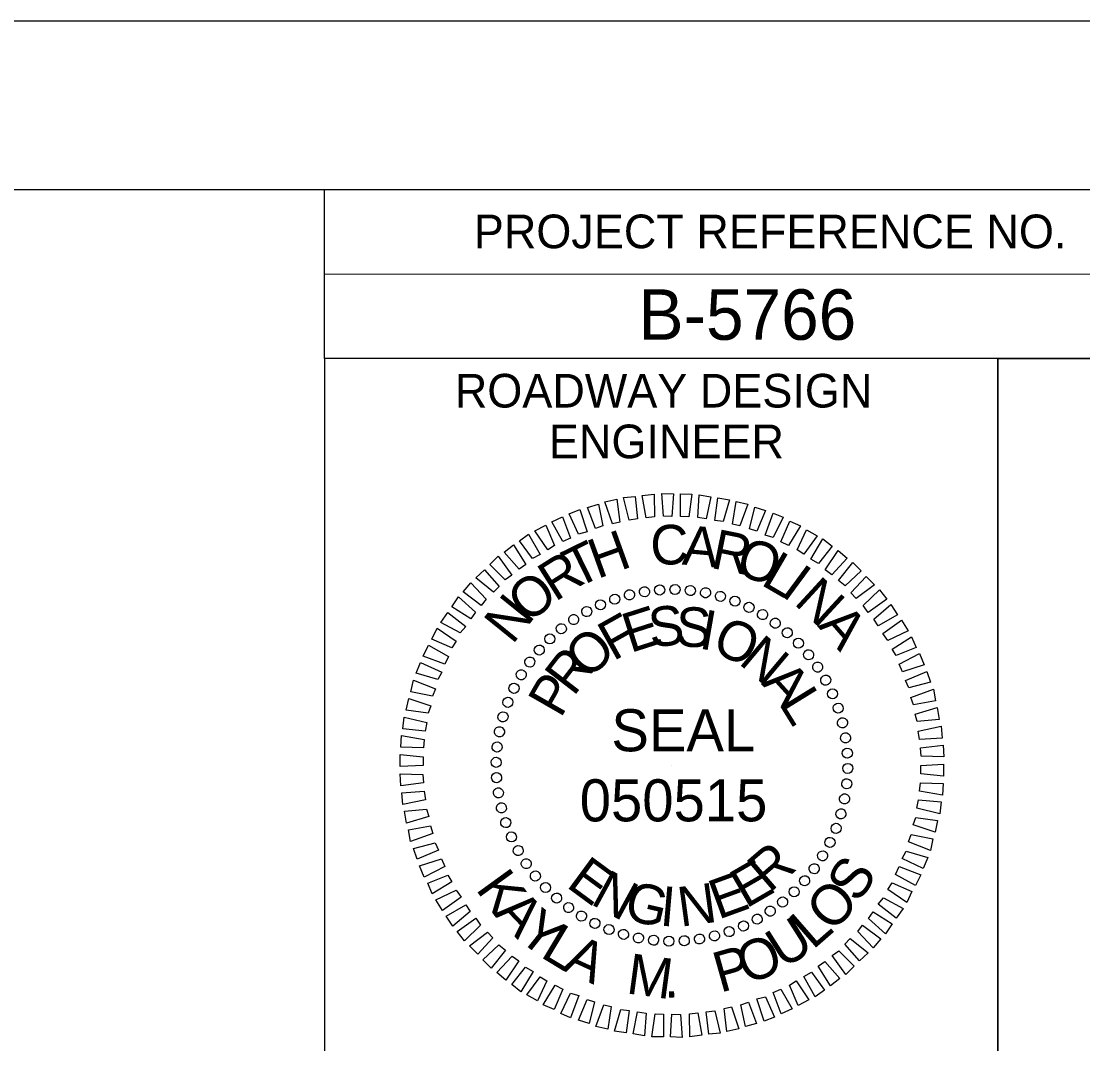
# Model space of a CAD drawing. Extents: x 573076.3 to 573113.7, y -55253.8 to -55199.3.
# Drawn here: x 573106.612 to 573109.767, y -55202.337 to -55199.298 of the extents above; entities that cross this region are included whole.
import ezdxf

# ---------------------------------------------------------------- set-up
doc = ezdxf.new("R2010")
doc.units = 0
for name, color, linetype in [('Prop Dimension', 7, 'Continuous'), ('Prop DSN Text', 7, 'Continuous'), ('Scratch_Level_1', 7, 'Continuous'), ('Sheet Plan CELL', 7, 'Continuous'), ('Sheet Plot Border Inside CELL', 7, 'Continuous')]:
    doc.layers.add(name, color=color, linetype=linetype)

msp = doc.modelspace()

# ---------------------------------------------------------------- linework, layer by layer
at = {"layer": 'Prop Dimension'}
for p, q in [((573108.4648, -55200.9939), (573108.4648, -55200.9939)), ((573108.5094, -55200.9876), (573108.5094, -55200.9876)), ((573108.5553, -55200.9867), (573108.5553, -55200.9867)), ((573108.6011, -55200.9897), (573108.6011, -55200.9897)), ((573108.646, -55200.9971), (573108.646, -55200.9971)), ((573108.3336, -55201.0314), (573108.3336, -55201.0314)), ((573108.3752, -55201.0147), (573108.3752, -55201.0147)), ((573108.419, -55201.0022), (573108.419, -55201.0022)), ((573108.6897, -55201.0064), (573108.6897, -55201.0064)), ((573108.7335, -55201.0209), (573108.7335, -55201.0209)), ((573108.2928, -55201.0522), (573108.2928, -55201.0522)), ((573108.7751, -55201.0397), (573108.7751, -55201.0397)), ((573108.8156, -55201.0605), (573108.8156, -55201.0605)), ((573108.2533, -55201.0762), (573108.2533, -55201.0762)), ((573108.8531, -55201.0867), (573108.8531, -55201.0867)), ((573108.2169, -55201.1022), (573108.2169, -55201.1022)), ((573108.8897, -55201.1147), (573108.8897, -55201.1147)), ((573108.1825, -55201.1334), (573108.1825, -55201.1334)), ((573108.9218, -55201.1459), (573108.9218, -55201.1459)), ((573108.1512, -55201.1658), (573108.1512, -55201.1658)), ((573108.9531, -55201.1804), (573108.9531, -55201.1804)), ((573108.1232, -55201.2021), (573108.1232, -55201.2021)), ((573108.9792, -55201.2167), (573108.9792, -55201.2167)), ((573108.0971, -55201.2396), (573108.0971, -55201.2396)), ((573108.0762, -55201.2804), (573108.0762, -55201.2804)), ((573109.0031, -55201.2563), (573109.0031, -55201.2563)), ((573109.0239, -55201.297), (573109.0239, -55201.297)), ((573108.0575, -55201.322), (573108.0575, -55201.322)), ((573109.0405, -55201.3387), (573109.0405, -55201.3387)), ((573108.0429, -55201.3658), (573108.0429, -55201.3658)), ((573108.0337, -55201.4095), (573108.0337, -55201.4095)), ((573109.053, -55201.3824), (573109.053, -55201.3824)), ((573109.0614, -55201.4282), (573109.0614, -55201.4282)), ((573108.0262, -55201.4542), (573108.0262, -55201.4542)), ((573109.0676, -55201.4729), (573109.0676, -55201.4729)), ((573108.0232, -55201.5), (573108.0232, -55201.5)), ((573108.546, -55201.5095), (573108.546, -55201.5095)), ((573109.0688, -55201.5187), (573109.0688, -55201.5187)), ((573108.0242, -55201.5458), (573108.0242, -55201.5458)), ((573109.0655, -55201.5645), (573109.0655, -55201.5645)), ((573108.0304, -55201.5907), (573108.0304, -55201.5907)), ((573109.0584, -55201.6094), (573109.0584, -55201.6094)), ((573108.0387, -55201.6365), (573108.0387, -55201.6365)), ((573109.0489, -55201.6532), (573109.0489, -55201.6532)), ((573108.0512, -55201.6802), (573108.0512, -55201.6802)), ((573108.0679, -55201.7219), (573108.0679, -55201.7219)), ((573109.0343, -55201.6969), (573109.0343, -55201.6969)), ((573109.0156, -55201.7386), (573109.0156, -55201.7386)), ((573108.0887, -55201.7624), (573108.0887, -55201.7624)), ((573108.9947, -55201.7791), (573108.9947, -55201.7791)), ((573108.1128, -55201.802), (573108.1128, -55201.802)), ((573108.9688, -55201.8166), (573108.9688, -55201.8166)), ((573108.1387, -55201.8385), (573108.1387, -55201.8385)), ((573108.9406, -55201.8531), (573108.9406, -55201.8531)), ((573108.17, -55201.8728), (573108.17, -55201.8728)), ((573108.2024, -55201.904), (573108.2024, -55201.904)), ((573108.9093, -55201.8853), (573108.9093, -55201.8853)), ((573108.2387, -55201.9323), (573108.2387, -55201.9323)), ((573108.8385, -55201.9427), (573108.8385, -55201.9427)), ((573108.8751, -55201.9165), (573108.8751, -55201.9165)), ((573108.2762, -55201.9582), (573108.2762, -55201.9582)), ((573108.3169, -55201.979), (573108.3169, -55201.979)), ((573108.7989, -55201.9665), (573108.7989, -55201.9665)), ((573108.3586, -55201.9977), (573108.3586, -55201.9977)), ((573108.7168, -55202.004), (573108.7168, -55202.004)), ((573108.7584, -55201.9873), (573108.7584, -55201.9873)), ((573108.4023, -55202.0123), (573108.4023, -55202.0123)), ((573108.446, -55202.0218), (573108.446, -55202.0218)), ((573108.4907, -55202.029), (573108.4907, -55202.029)), ((573108.5365, -55202.0322), (573108.5365, -55202.0322)), ((573108.5823, -55202.0311), (573108.5823, -55202.0311)), ((573108.6272, -55202.0248), (573108.6272, -55202.0248)), ((573108.6731, -55202.0165), (573108.6731, -55202.0165))]:
    msp.add_line(p, q, dxfattribs=at)
for points in [[(573108.419, -55200.7805), (573108.4023, -55200.7138), (573108.4365, -55200.7106), (573108.444, -55200.7773)], [(573108.4689, -55200.7742), (573108.4574, -55200.7076), (573108.4928, -55200.7034), (573108.4939, -55200.771)], [(573108.521, -55200.7689), (573108.5157, -55200.7014), (573108.5502, -55200.7023), (573108.546, -55200.7701)], [(573108.571, -55200.7701), (573108.571, -55200.7023), (573108.6053, -55200.7034), (573108.596, -55200.771)], [(573108.6231, -55200.7731), (573108.6272, -55200.7055), (573108.6615, -55200.7118), (573108.6481, -55200.7773)], [(573108.6731, -55200.7814), (573108.6823, -55200.7148), (573108.7168, -55200.7201), (573108.6981, -55200.7847)], [(573108.319, -55200.8055), (573108.2949, -55200.743), (573108.3273, -55200.7335), (573108.3407, -55200.7981)], [(573108.369, -55200.7918), (573108.347, -55200.7263), (573108.3824, -55200.7189), (573108.3907, -55200.7867)], [(573108.7261, -55200.793), (573108.7365, -55200.7252), (573108.7719, -55200.7335), (573108.748, -55200.7981)], [(573108.776, -55200.8064), (573108.7918, -55200.7418), (573108.8239, -55200.7523), (573108.798, -55200.8138)], [(573108.222, -55200.8439), (573108.1887, -55200.7856), (573108.2211, -55200.771), (573108.2449, -55200.8346)], [(573108.2678, -55200.8221), (573108.2408, -55200.7617), (573108.272, -55200.7493), (573108.294, -55200.8159)], [(573108.823, -55200.8252), (573108.8468, -55200.7597), (573108.876, -55200.7722), (573108.8469, -55200.8326)], [(573108.1774, -55200.8689), (573108.1387, -55200.8127), (573108.1711, -55200.796), (573108.197, -55200.8564)], [(573108.8698, -55200.8451), (573108.8959, -55200.7835), (573108.9281, -55200.7981), (573108.8927, -55200.8564)], [(573108.9177, -55200.8689), (573108.9459, -55200.8097), (573108.9771, -55200.8272), (573108.9376, -55200.8814)], [(573108.1315, -55200.895), (573108.0929, -55200.8418), (573108.12, -55200.8222), (573108.1544, -55200.8825)], [(573108.9584, -55200.8971), (573108.9947, -55200.8367), (573109.0218, -55200.8585), (573108.9813, -55200.9096)], [(573108.092, -55200.9263), (573108.0471, -55200.8763), (573108.0753, -55200.8543), (573108.1116, -55200.9126)], [(573109.001, -55200.9284), (573109.0396, -55200.871), (573109.0667, -55200.8939), (573109.0209, -55200.943)], [(573108.0503, -55200.9585), (573108.0045, -55200.9126), (573108.0295, -55200.8876), (573108.07, -55200.9439)], [(573109.0405, -55200.9605), (573109.0834, -55200.9064), (573109.1084, -55200.9314), (573109.0604, -55200.9763)], [(573108.0158, -55200.995), (573107.9628, -55200.9522), (573107.9888, -55200.9284), (573108.0325, -55200.9784)], [(573107.9795, -55201.0346), (573107.9253, -55200.9939), (573107.9483, -55200.9668), (573107.9941, -55201.0158)], [(573109.078, -55200.9971), (573109.1229, -55200.948), (573109.1479, -55200.973), (573109.0938, -55201.0138)], [(573109.1146, -55201.0346), (573109.1625, -55200.9876), (573109.1843, -55201.0158), (573109.1292, -55201.0554)], [(573107.9483, -55201.0742), (573107.892, -55201.0388), (573107.9117, -55201.0084), (573107.9617, -55201.0543)], [(573109.1458, -55201.0751), (573109.1968, -55201.0314), (573109.2167, -55201.0617), (573109.1583, -55201.095)], [(573107.917, -55201.1158), (573107.8587, -55201.0846), (573107.8795, -55201.0554), (573107.9337, -55201.0971)], [(573109.1729, -55201.1179), (573109.228, -55201.0783), (573109.2479, -55201.1096), (573109.1875, -55201.1387)], [(573107.892, -55201.1605), (573107.8325, -55201.1346), (573107.8483, -55201.1022), (573107.9045, -55201.1408)], [(573109.2, -55201.1637), (573109.2583, -55201.1272), (573109.2717, -55201.1596), (573109.2125, -55201.1834)], [(573107.8712, -55201.2084), (573107.8066, -55201.1846), (573107.8221, -55201.1522), (573107.8816, -55201.1855)], [(573109.2208, -55201.2084), (573109.2821, -55201.1771), (573109.2958, -55201.2105), (573109.2312, -55201.2313)], [(573107.8504, -55201.2542), (573107.7858, -55201.2355), (573107.7992, -55201.2033), (573107.8617, -55201.2325)], [(573109.2396, -55201.2574), (573109.303, -55201.2304), (573109.3145, -55201.2625), (573109.25, -55201.2792)], [(573107.8346, -55201.3042), (573107.7701, -55201.2908), (573107.7775, -55201.2563), (573107.843, -55201.2824)], [(573109.2562, -55201.3074), (573109.3229, -55201.2834), (573109.3291, -55201.3178), (573109.2634, -55201.3292)], [(573107.8212, -55201.3542), (573107.7566, -55201.3458), (573107.7638, -55201.3104), (573107.8295, -55201.3324)], [(573109.2687, -55201.3574), (573109.3342, -55201.3375), (573109.3405, -55201.3729), (573109.275, -55201.3792)], [(573107.8129, -55201.4074), (573107.7462, -55201.4012), (573107.7504, -55201.3658), (573107.818, -55201.3824)], [(573109.278, -55201.4074), (573109.3458, -55201.3928), (573109.3488, -55201.4282), (573109.2821, -55201.4324)], [(573107.8076, -55201.4574), (573107.74, -55201.4553), (573107.7421, -55201.4208), (573107.8096, -55201.4324)], [(573109.2842, -55201.4574), (573109.352, -55201.4491), (573109.3541, -55201.4845), (573109.2863, -55201.4824)], [(573107.8066, -55201.5095), (573107.7388, -55201.5125), (573107.7388, -55201.4771), (573107.8066, -55201.4845)], [(573109.2854, -55201.5095), (573109.353, -55201.5062), (573109.353, -55201.5416), (573109.2854, -55201.5345)], [(573107.8076, -55201.5615), (573107.74, -55201.5699), (573107.7379, -55201.5345), (573107.8055, -55201.5365)], [(573109.2842, -55201.5615), (573109.352, -55201.5636), (573109.35, -55201.5979), (573109.2821, -55201.5865)], [(573107.8138, -55201.6115), (573107.7462, -55201.6261), (573107.743, -55201.5907), (573107.8096, -55201.5865)], [(573109.2791, -55201.6115), (573109.3458, -55201.6178), (573109.3416, -55201.6532), (573109.2738, -55201.6365)], [(573107.8233, -55201.6615), (573107.7576, -55201.6812), (573107.7513, -55201.6458), (573107.817, -55201.6395)], [(573107.8358, -55201.7115), (573107.7691, -55201.7353), (573107.7629, -55201.7011), (573107.8284, -55201.6895)], [(573109.2708, -55201.6645), (573109.3354, -55201.6728), (573109.328, -55201.7082), (573109.2625, -55201.6865)], [(573109.2572, -55201.7145), (573109.3217, -55201.7281), (573109.3145, -55201.7624), (573109.2488, -55201.7365)], [(573107.8524, -55201.7615), (573107.7888, -55201.7885), (573107.7775, -55201.7562), (573107.842, -55201.7395)], [(573107.8712, -55201.8103), (573107.8096, -55201.8415), (573107.7962, -55201.8082), (573107.8608, -55201.7874)], [(573109.2416, -55201.7645), (573109.3062, -55201.7832), (573109.2926, -55201.8156), (573109.2301, -55201.7865)], [(573109.2208, -55201.8103), (573109.2854, -55201.8344), (573109.2696, -55201.8665), (573109.2104, -55201.8332)], [(573107.892, -55201.8552), (573107.8337, -55201.8915), (573107.8201, -55201.8594), (573107.8795, -55201.8353)], [(573107.9191, -55201.901), (573107.8638, -55201.9406), (573107.8441, -55201.9093), (573107.9045, -55201.8802)], [(573109.2, -55201.8582), (573109.2592, -55201.8844), (573109.2437, -55201.9165), (573109.1875, -55201.8781)], [(573109.175, -55201.9031), (573109.2333, -55201.9343), (573109.2125, -55201.9635), (573109.1583, -55201.9218)], [(573107.9462, -55201.9436), (573107.895, -55201.9873), (573107.8754, -55201.9573), (573107.9337, -55201.9239)], [(573109.1438, -55201.9448), (573109.2, -55201.9802), (573109.1801, -55202.0102), (573109.1301, -55201.9644)], [(573107.9774, -55201.9843), (573107.9295, -55202.0311), (573107.9075, -55202.0031), (573107.9628, -55201.9635)], [(573108.0137, -55202.0218), (573107.9691, -55202.0706), (573107.9441, -55202.0457), (573107.9982, -55202.0052)], [(573109.1125, -55201.9843), (573109.1667, -55202.0248), (573109.1438, -55202.0519), (573109.0979, -55202.0031)], [(573109.076, -55202.0239), (573109.1292, -55202.0665), (573109.103, -55202.0906), (573109.0593, -55202.0406)], [(573108.0512, -55202.0581), (573108.0087, -55202.1123), (573107.9837, -55202.0873), (573108.0316, -55202.0426)], [(573109.0417, -55202.0602), (573109.0875, -55202.1061), (573109.0625, -55202.131), (573109.0218, -55202.0748)], [(573108.0908, -55202.0906), (573108.0524, -55202.1477), (573108.0253, -55202.1248), (573108.0711, -55202.076)], [(573109.0001, -55202.0926), (573109.0447, -55202.1426), (573109.0167, -55202.1644), (573108.9801, -55202.1061)], [(573108.1336, -55202.1218), (573108.0971, -55202.1822), (573108.07, -55202.1602), (573108.1107, -55202.1093)], [(573108.9605, -55202.1239), (573108.9989, -55202.1769), (573108.9718, -55202.1968), (573108.9376, -55202.1364)], [(573108.1741, -55202.1498), (573108.1461, -55202.2093), (573108.1149, -55202.1914), (573108.1544, -55202.1373)], [(573108.222, -55202.1739), (573108.1961, -55202.2352), (573108.1637, -55202.2206), (573108.1991, -55202.1623)], [(573108.9147, -55202.1498), (573108.9531, -55202.206), (573108.9209, -55202.2227), (573108.8948, -55202.1623)], [(573108.269, -55202.1935), (573108.2449, -55202.2592), (573108.2158, -55202.2468), (573108.2449, -55202.1864)], [(573108.8239, -55202.1968), (573108.851, -55202.2572), (573108.8198, -55202.2697), (573108.798, -55202.203)], [(573108.8698, -55202.1748), (573108.9031, -55202.2331), (573108.8709, -55202.2477), (573108.8468, -55202.1843)], [(573108.3158, -55202.2123), (573108.3002, -55202.2768), (573108.2678, -55202.2664), (573108.294, -55202.2051)], [(573108.3657, -55202.2259), (573108.3553, -55202.2935), (573108.3199, -55202.2852), (573108.344, -55202.2206)], [(573108.723, -55202.2269), (573108.7448, -55202.2926), (573108.7094, -55202.2997), (573108.7011, -55202.2322)], [(573108.773, -55202.2134), (573108.7969, -55202.2759), (573108.7647, -55202.2852), (573108.751, -55202.2206)], [(573108.419, -55202.2373), (573108.4095, -55202.3039), (573108.3752, -55202.2988), (573108.394, -55202.2343)], [(573108.4689, -55202.2456), (573108.4648, -55202.3134), (573108.4303, -55202.3072), (573108.444, -55202.2414)], [(573108.521, -55202.2488), (573108.521, -55202.3164), (573108.4865, -55202.3155), (573108.496, -55202.2477)], [(573108.571, -55202.2498), (573108.5761, -55202.3176), (573108.5418, -55202.3164), (573108.546, -55202.2488)], [(573108.6231, -55202.2447), (573108.6344, -55202.3113), (573108.599, -55202.3155), (573108.5981, -55202.2477)], [(573108.6731, -55202.2384), (573108.6897, -55202.3051), (573108.6552, -55202.3081), (573108.6481, -55202.2414)]]:
    msp.add_lwpolyline(points, close=True, dxfattribs=at)
for centre, major_axis in [((573108.376, -55201.0155), (-0.0049, 0.0142)), ((573108.4196, -55201.0026), (-0.0036, 0.0146)), ((573108.4643, -55200.9935), (-0.0023, 0.0148)), ((573108.5096, -55200.9883), (-0.001, 0.015)), ((573108.5551, -55200.9871), (0.0003, 0.015)), ((573108.6006, -55200.9899), (0.0016, 0.0149)), ((573108.6457, -55200.9966), (0.0029, 0.0147)), ((573108.69, -55201.0073), (0.0041, 0.0144)), ((573108.3336, -55201.0322), (-0.0061, 0.0137)), ((573108.7332, -55201.0217), (0.0054, 0.014)), ((573108.775, -55201.0399), (0.0066, 0.0135)), ((573108.2539, -55201.0763), (-0.0084, 0.0124)), ((573108.2928, -55201.0525), (-0.0073, 0.0131)), ((573108.8151, -55201.0616), (0.0077, 0.0129)), ((573108.2173, -55201.1034), (-0.0094, 0.0117)), ((573108.8531, -55201.0868), (0.0088, 0.0121)), ((573108.1832, -55201.1336), (-0.0104, 0.0108)), ((573108.8887, -55201.1152), (0.0098, 0.0113)), ((573108.1518, -55201.1667), (-0.0113, 0.0098)), ((573108.9218, -55201.1465), (0.0108, 0.0104)), ((573108.1234, -55201.2024), (-0.0121, 0.0088)), ((573108.952, -55201.1807), (0.0117, 0.0094)), ((573108.9791, -55201.2173), (0.0124, 0.0084)), ((573108.0983, -55201.2404), (-0.0129, 0.0077)), ((573109.0029, -55201.2562), (0.0131, 0.0073)), ((573108.0765, -55201.2804), (-0.0135, 0.0066)), ((573109.0232, -55201.2969), (0.0137, 0.0061)), ((573108.0584, -55201.3222), (-0.014, 0.0054)), ((573109.0399, -55201.3393), (0.0142, 0.0049)), ((573108.0439, -55201.3654), (-0.0144, 0.0041)), ((573109.0529, -55201.383), (0.0146, 0.0036)), ((573108.0333, -55201.4097), (-0.0147, 0.0029)), ((573109.0619, -55201.4277), (0.0148, 0.0023)), ((573108.0265, -55201.4548), (-0.0149, 0.0016)), ((573109.0671, -55201.473), (0.015, 0.001)), ((573108.0237, -55201.5003), (-0.015, 0.0003)), ((573109.0683, -55201.5185), (0.015, -0.0003)), ((573108.0249, -55201.5458), (-0.015, -0.001)), ((573109.0655, -55201.564), (0.0149, -0.0016)), ((573108.0301, -55201.5911), (-0.0148, -0.0023)), ((573109.0588, -55201.6091), (0.0147, -0.0029)), ((573108.0392, -55201.6358), (-0.0146, -0.0036)), ((573108.0521, -55201.6795), (-0.0142, -0.0049)), ((573109.0481, -55201.6534), (0.0144, -0.0041)), ((573109.0337, -55201.6966), (0.014, -0.0054)), ((573108.0688, -55201.7219), (-0.0137, -0.0061)), ((573109.0155, -55201.7384), (0.0135, -0.0066)), ((573108.0892, -55201.7626), (-0.0131, -0.0073)), ((573108.113, -55201.8015), (-0.0124, -0.0084)), ((573108.9938, -55201.7784), (0.0129, -0.0077)), ((573108.1401, -55201.8381), (-0.0117, -0.0094)), ((573108.9686, -55201.8164), (0.0121, -0.0088)), ((573108.9402, -55201.8521), (0.0113, -0.0098)), ((573108.1703, -55201.8723), (-0.0108, -0.0104)), ((573108.9089, -55201.8851), (0.0104, -0.0108)), ((573108.2033, -55201.9036), (-0.0098, -0.0113)), ((573108.239, -55201.932), (-0.0088, -0.0121)), ((573108.8747, -55201.9153), (0.0094, -0.0117)), ((573108.277, -55201.9571), (-0.0077, -0.0129)), ((573108.8381, -55201.9424), (0.0084, -0.0124)), ((573108.317, -55201.9789), (-0.0066, -0.0135)), ((573108.7585, -55201.9866), (0.0061, -0.0137)), ((573108.7993, -55201.9663), (0.0073, -0.0131)), ((573108.3588, -55201.9971), (-0.0054, -0.014)), ((573108.402, -55202.0115), (-0.0041, -0.0144)), ((573108.4463, -55202.0222), (-0.0029, -0.0147)), ((573108.6277, -55202.0253), (0.0023, -0.0148)), ((573108.6724, -55202.0162), (0.0036, -0.0146)), ((573108.7161, -55202.0033), (0.0049, -0.0142)), ((573108.4914, -55202.0289), (-0.0016, -0.0149)), ((573108.5369, -55202.0317), (-0.0003, -0.015)), ((573108.5825, -55202.0305), (0.001, -0.015))]:
    msp.add_ellipse(centre, major_axis=major_axis, ratio=0.999708, dxfattribs=at)
at = {"layer": 'Scratch_Level_1'}
msp.add_line((573108.546, -55201.5095), (573108.546, -55201.5095), dxfattribs=at)
at = {"layer": 'Sheet Plan CELL'}
for p, q in [((573107.5132, -55200.0494), (573111.5142, -55200.0497)), ((573109.5142, -55200.3002), (573109.5144, -55202.5494))]:
    msp.add_line(p, q, dxfattribs=at)
for points in [[(573081.5142, -55199.7984), (573111.5142, -55199.7984), (573111.5142, -55220.7984), (573081.5142, -55220.7984)], [(573107.5132, -55199.7984), (573111.5142, -55199.7984), (573111.5142, -55200.3002), (573107.5132, -55200.3002)], [(573109.5142, -55200.3002), (573107.5132, -55200.3002), (573107.5132, -55202.5502), (573109.5142, -55202.5502)], [(573109.5142, -55200.3002), (573111.5142, -55200.3002), (573111.5142, -55202.5502), (573109.5142, -55202.5502)]]:
    msp.add_lwpolyline(points, close=True, dxfattribs=at)
at = {"layer": 'Sheet Plot Border Inside CELL'}
msp.add_lwpolyline([(573112.0142, -55199.2984), (573078.0142, -55199.2984), (573078.0142, -55221.2984), (573112.0142, -55221.2984)], close=True, dxfattribs=at)

# ---------------------------------------------------------------- texts
at = {"layer": 'Prop Dimension'}
for s, height, rotation, p in [('H', 0.1177, 19.8207, (573108.3243, -55200.9561)), ('C', 0.1177, 1.0718, (573108.4826, -55200.9136)), ('A', 0.1177, 354.8222, (573108.5742, -55200.9124)), ('R', 0.1177, 348.5725, (573108.6576, -55200.9219)), ('T', 0.1177, 26.0703, (573108.2609, -55200.9853)), ('O', 0.1177, 342.3229, (573108.7304, -55200.9406)), ('R', 0.1177, 32.3199, (573108.1984, -55201.0249)), ('L', 0.1177, 329.8237, (573108.8066, -55200.9707)), ('I', 0.1177, 323.5741, (573108.8649, -55201.001)), ('O', 0.1177, 38.5695, (573108.1181, -55201.0906)), ('N', 0.1177, 317.3244, (573108.9054, -55201.0281)), ('N', 0.1177, 51.0688, (573108.0714, -55201.1531)), ('S', 0.1177, 6.1833, (573108.4826, -55201.1593)), ('F', 0.1177, 29.3, (573108.3713, -55201.201)), ('E', 0.1177, 17.6709, (573108.4222, -55201.176)), ('S', 0.1177, 358.4778, (573108.5567, -55201.1561)), ('I', 0.1177, 350.0931, (573108.6233, -55201.1614)), ('A', 0.1177, 311.0748, (573108.9774, -55201.0957)), ('O', 0.1177, 335.3611, (573108.6596, -55201.1686)), ('O', 0.1177, 43.5875, (573108.2972, -55201.2572)), ('N', 0.1177, 319.95, (573108.7409, -55201.2051)), ('R', 0.1177, 52.4166, (573108.2535, -55201.3072)), ('A', 0.1177, 312.2445, (573108.8096, -55201.2665)), ('P', 0.1177, 60.1222, (573108.2151, -55201.3718)), ('L', 0.1177, 301.6752, (573108.8617, -55201.3248)), ('SEAL', 0.12497, 360, (573108.366, -55201.4676)), ('050515', 0.12497, 360, (573108.2719, -55201.6758)), ('R', 0.1177, 40.7353, (573108.8357, -55201.8904)), ('E', 0.1177, 323.6798, (573108.2285, -55201.8684)), ('E', 0.1177, 30.1214, (573108.7659, -55201.9362)), ('S', 0.12, 57.1863, (573109.1004, -55201.9217)), ('K', 0.12, 305.9043, (573107.9606, -55201.8764)), ('N', 0.1177, 331.3854, (573108.3005, -55201.9195)), ('E', 0.1177, 20.0411, (573108.6837, -55201.9684)), ('G', 0.1177, 346.7965, (573108.3993, -55201.9654)), ('I', 0.1177, 355.0405, (573108.5076, -55201.985)), ('N', 0.1177, 7.7341, (573108.5712, -55201.9892)), ('O', 0.12, 47.4888, (573109.0231, -55202.0092)), ('A', 0.12, 313.5599, (573108.0147, -55201.9511)), ('Y', 0.12, 321.5623, (573108.0814, -55202.0208)), ('U', 0.12, 32.399, (573108.8765, -55202.1162)), ('L', 0.12, 41.0852, (573108.9643, -55202.0593)), ('L', 0.12, 328.9868, (573108.1513, -55202.0766)), ('A', 0.12, 335.3904, (573108.2171, -55202.117)), ('O', 0.12, 22.7015, (573108.7696, -55202.1632)), ('M', 0.12, 352.2427, (573108.4073, -55202.1863)), ('P', 0.12, 15.7778, (573108.6891, -55202.1854)), ('.', 0.12, 1.9209, (573108.5231, -55202.2))]:
    msp.add_text(s, height=height, rotation=rotation, dxfattribs=at).set_placement(p)
at = {"layer": 'Prop DSN Text'}
msp.add_text('B-5766', height=0.15, rotation=0, dxfattribs=at).set_placement((573108.4467, -55200.2449))
at = {"layer": 'Sheet Plan CELL'}
for s, height, p in [('PROJECT REFERENCE NO.', 0.100002, (573107.9572, -55199.9729)), ('ROADWAY DESIGN', 0.100002, (573107.9007, -55200.4462)), ('ENGINEER', 0.1, (573108.1804, -55200.5969))]:
    msp.add_text(s, height=height, rotation=0, dxfattribs=at).set_placement(p)

doc.saveas('drawing.dxf')
